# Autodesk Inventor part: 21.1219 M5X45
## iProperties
Created: 2006-02
Part Number: 21.1219 M5X45
Material: Steel, Mild
Description: Cylinder Head Cap Screw
Document SubType Name: Modeling
Standard: DIN 7984
Designer: Andy Moles
Standards Organization: DIN
Language: en-US
Size Designation: M5 x 30
Categories: <MemberInstance><Categories><Category DisplayName="Fasteners" InternalName="e4da775c-781d-43d5-af7c-5136215cf5a6" Mnemonic="FSTN"><Category DisplayName="Bolts"
Density: 1 g/cm^3
Author: Andy Moles
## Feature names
1. Body [Revolution]
2. Slot [Extrusion]
3. Fillet1
4. Chamfer1
